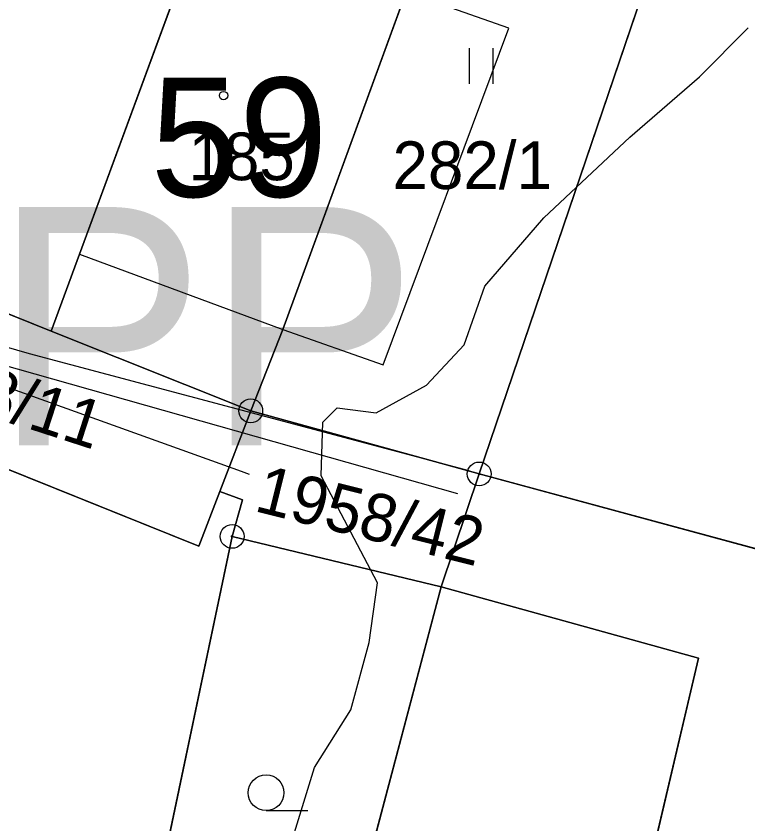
# Model space of a CAD drawing. Extents: x -706130 to -698555, y -971544 to -967260.
# Drawn here: x -704307.34 to -704276.64, y -970193.24 to -970159.33 of the extents above; entities that cross this region are included whole.
import ezdxf

# ---------------------------------------------------------------- set-up
doc = ezdxf.new("R2010")
doc.units = 0
for name, color, linetype in [('_Doplněk budov pro zastavěnost', 7, 'Continuous'), ('BPEJ I-II trida ochrany S', 7, 'Continuous'), ('Docházková izochrona - BUS S', 7, 'Continuous'), ('Docházková izochrona - VLAK N', 7, 'Continuous'), ('Kanalizace_stoka bez rozlišení N', 7, 'Continuous'), ('KN_Budovy', 7, 'Continuous'), ('KN_Budovy_cisla_domovni', 7, 'Continuous'), ('KN_Hranice_parcel', 7, 'Continuous'), ('KN_Hranice_parcel_vnitrni_kresba', 7, 'Continuous'), ('KN_Parcelni cisla', 7, 'Continuous'), ('KN_Polygon parcely', 7, 'Continuous'), ('KN_POZEMKY_13_ZASTAVENA PLOCHA', 7, 'Continuous'), ('KN_POZEMKY_14_OSTATNI PLOCHA', 7, 'Continuous'), ('KN_POZEMKY_5_ZAHRADA', 7, 'Continuous'), ('KN_POZEMKY_7_TTP', 7, 'Continuous'), ('KN_VYUZITI_17_ostatni plocha_ostatni komunikace', 7, 'Continuous'), ('KN_Značky bodu BP', 7, 'Continuous'), ('KN_Značky budov', 7, 'Continuous'), ('KN_Značky kultur', 7, 'Continuous'), ('Plochy smíšené obytné venkovské S', 7, 'Continuous'), ('Plochy verejnych prostranstvi - komunikace ostatni S', 7, 'Continuous'), ('Plynovody STL S', 7, 'Continuous'), ('Regulační bloky zastavěné S', 7, 'Continuous'), ('Regulační kódy zastavěné S', 7, 'Continuous'), ('Vodovodní řady - rozváděcí S', 7, 'Continuous'), ('Záplavové území stanovene S', 7, 'Continuous')]:
    doc.layers.add(name, color=color, linetype=linetype)

msp = doc.modelspace()

# ---------------------------------------------------------------- linework, layer by layer
at = {"layer": '_Doplněk budov pro zastavěnost'}
msp.add_line((-704290.97, -970158.31), (-704296.15, -970172.48), dxfattribs=at)
msp.add_lwpolyline([(-704296.15, -970172.48), (-704291.936, -970173.974), (-704286.668, -970159.832), (-704290.97, -970158.31)], dxfattribs=at)
at = {"layer": 'BPEJ I-II trida ochrany S'}
for p, q in [((-704304.68, -970169.32), (-704299.48, -970155.18)), ((-704290.97, -970158.31), (-704296.15, -970172.48)), ((-704313.84, -970169.35), (-704305.87, -970172.55)), ((-704305.87, -970172.55), (-704304.68, -970169.32)), ((-704296.15, -970172.48), (-704297.5, -970175.9)), ((-704297.5, -970175.9), (-704287.91, -970178.55)), ((-704287.91, -970178.55), (-704274.42, -970182.2)), ((-704298.28, -970181.17), (-704303.37, -970205.4)), ((-704289.51, -970183.29), (-704298.28, -970181.17)), ((-704278.71, -970186.28), (-704289.51, -970183.29)), ((-704281.59, -970198.52), (-704278.71, -970186.28))]:
    msp.add_line(p, q, dxfattribs=at)
at = {"layer": 'Docházková izochrona - BUS S'}
msp.add_arc((-704361.829, -969946.93), 400, 155.51821, 17.33949, dxfattribs=at)
at = {"layer": 'Docházková izochrona - VLAK N'}
msp.add_circle((-704165.451, -969778.767), 800, dxfattribs=at)
at = {"layer": 'Kanalizace_stoka bez rozlišení N'}
msp.add_lwpolyline([(-704326.245, -970169.76), (-704311.212, -970173.028), (-704288.826, -970179.373)], dxfattribs=at)
at = {"layer": 'KN_Budovy'}
msp.add_lwpolyline([(-704299.48, -970155.18), (-704304.68, -970169.32), (-704296.15, -970172.48), (-704290.97, -970158.31)], close=True, dxfattribs=at)
at = {"layer": 'KN_Hranice_parcel'}
for p, q in [((-704287.91, -970178.55), (-704277.5, -970147.92)), ((-704313.84, -970169.35), (-704305.87, -970172.55)), ((-704305.87, -970172.55), (-704297.5, -970175.9)), ((-704298.79, -970179.28), (-704297.5, -970175.9)), ((-704297.5, -970175.9), (-704287.91, -970178.55)), ((-704287.91, -970178.55), (-704289.51, -970183.29)), ((-704303.37, -970205.4), (-704298.28, -970181.17)), ((-704289.51, -970183.29), (-704298.28, -970181.17)), ((-704289.51, -970183.29), (-704295.97, -970207.7))]:
    msp.add_line(p, q, dxfattribs=at)
for points in [[(-704290.97, -970158.31), (-704299.48, -970155.18), (-704304.68, -970169.32), (-704305.87, -970172.55)], [(-704297.5, -970175.9), (-704296.15, -970172.48), (-704290.97, -970158.31)], [(-704229.48, -970192.46), (-704233.16, -970192.68), (-704246.9, -970190.81), (-704243.81, -970184.46), (-704246.58, -970183.12), (-704250.99, -970180.98), (-704248.44, -970175.82), (-704254.77, -970172.57), (-704251.76, -970166.35), (-704257.7, -970163.48), (-704260.71, -970169.69), (-704266.92, -970166.69), (-704270.32, -970173.72), (-704274.42, -970182.2), (-704287.91, -970178.55)], [(-704298.79, -970179.28), (-704299.67, -970181.58), (-704316.23, -970174.92), (-704322.1, -970177.43), (-704324.27, -970184.8)], [(-704298.28, -970181.17), (-704297.85, -970179.64), (-704298.79, -970179.28)], [(-704289.51, -970183.29), (-704278.71, -970186.28), (-704281.59, -970198.52), (-704273.81, -970199.62), (-704275.41, -970210.91)]]:
    msp.add_lwpolyline(points, dxfattribs=at)
at = {"layer": 'KN_Hranice_parcel_vnitrni_kresba'}
msp.add_line((-704304.68, -970169.32), (-704296.15, -970172.48), dxfattribs=at)
at = {"layer": 'KN_Polygon parcely'}
for points in [[(-704305.87, -970172.55), (-704304.68, -970169.32), (-704299.48, -970155.18), (-704290.97, -970158.31), (-704288.36, -970145.25), (-704300.38, -970142.47), (-704313.84, -970169.35)], [(-704287.91, -970178.55), (-704277.5, -970147.92), (-704288.36, -970145.25), (-704290.97, -970158.31), (-704296.15, -970172.48), (-704297.5, -970175.9)], [(-704229.48, -970192.46), (-704222.31, -970155.39), (-704260.52, -970150.22), (-704277.5, -970147.92), (-704287.91, -970178.55), (-704274.42, -970182.2), (-704270.32, -970173.72), (-704266.92, -970166.69), (-704260.71, -970169.69), (-704257.7, -970163.48), (-704251.76, -970166.35), (-704254.77, -970172.57), (-704248.44, -970175.82), (-704250.99, -970180.98), (-704246.58, -970183.12), (-704243.81, -970184.46), (-704246.9, -970190.81), (-704233.16, -970192.68)], [(-704290.97, -970158.31), (-704299.48, -970155.18), (-704304.68, -970169.32), (-704305.87, -970172.55), (-704297.5, -970175.9), (-704296.15, -970172.48)], [(-704297.5, -970175.9), (-704305.87, -970172.55), (-704313.84, -970169.35), (-704322.68, -970165.89), (-704322.52, -970176.47), (-704324.27, -970184.8), (-704322.1, -970177.43), (-704316.23, -970174.92), (-704299.67, -970181.58), (-704298.79, -970179.28)], [(-704316.23, -970174.92), (-704322.1, -970177.43), (-704324.27, -970184.8), (-704325.58, -970189.23), (-704327.21, -970194.48), (-704328.2, -970197.68), (-704303.37, -970205.4), (-704298.28, -970181.17), (-704297.85, -970179.64), (-704298.79, -970179.28), (-704299.67, -970181.58)], [(-704298.79, -970179.28), (-704297.85, -970179.64), (-704298.28, -970181.17), (-704289.51, -970183.29), (-704287.91, -970178.55), (-704297.5, -970175.9)], [(-704303.37, -970205.4), (-704295.97, -970207.7), (-704289.51, -970183.29), (-704298.28, -970181.17)], [(-704289.51, -970183.29), (-704295.97, -970207.7), (-704281.8, -970209.65), (-704275.41, -970210.91), (-704273.81, -970199.62), (-704281.59, -970198.52), (-704278.71, -970186.28)]]:
    msp.add_lwpolyline(points, close=True, dxfattribs=at)
msp.add_lwpolyline([(-704230.21, -970196.19), (-704229.48, -970192.46), (-704233.16, -970192.68), (-704246.9, -970190.81), (-704243.81, -970184.46), (-704246.58, -970183.12), (-704250.99, -970180.98), (-704248.44, -970175.82), (-704254.77, -970172.57), (-704251.76, -970166.35), (-704257.7, -970163.48), (-704260.71, -970169.69), (-704266.92, -970166.69), (-704270.32, -970173.72), (-704274.42, -970182.2), (-704287.91, -970178.55), (-704289.51, -970183.29), (-704278.71, -970186.28), (-704281.59, -970198.52)], dxfattribs=at)
at = {"layer": 'KN_POZEMKY_13_ZASTAVENA PLOCHA'}
for p, q in [((-704304.68, -970169.32), (-704299.48, -970155.18)), ((-704290.97, -970158.31), (-704296.15, -970172.48)), ((-704305.87, -970172.55), (-704304.68, -970169.32)), ((-704296.15, -970172.48), (-704297.5, -970175.9)), ((-704297.5, -970175.9), (-704305.87, -970172.55)), ((-704316.23, -970174.92), (-704299.67, -970181.58)), ((-704289.51, -970183.29), (-704287.91, -970178.55)), ((-704287.91, -970178.55), (-704274.42, -970182.2)), ((-704299.67, -970181.58), (-704298.79, -970179.28)), ((-704298.79, -970179.28), (-704297.85, -970179.64)), ((-704297.85, -970179.64), (-704298.28, -970181.17)), ((-704298.28, -970181.17), (-704303.37, -970205.4)), ((-704278.71, -970186.28), (-704289.51, -970183.29)), ((-704281.59, -970198.52), (-704278.71, -970186.28))]:
    msp.add_line(p, q, dxfattribs=at)
at = {"layer": 'KN_POZEMKY_14_OSTATNI PLOCHA'}
for p, q in [((-704313.84, -970169.35), (-704305.87, -970172.55)), ((-704305.87, -970172.55), (-704297.5, -970175.9)), ((-704299.67, -970181.58), (-704316.23, -970174.92)), ((-704297.5, -970175.9), (-704298.79, -970179.28)), ((-704298.79, -970179.28), (-704297.5, -970175.9)), ((-704297.5, -970175.9), (-704287.91, -970178.55)), ((-704287.91, -970178.55), (-704289.51, -970183.29)), ((-704298.79, -970179.28), (-704299.67, -970181.58)), ((-704297.85, -970179.64), (-704298.79, -970179.28)), ((-704298.28, -970181.17), (-704297.85, -970179.64)), ((-704289.51, -970183.29), (-704298.28, -970181.17))]:
    msp.add_line(p, q, dxfattribs=at)
at = {"layer": 'KN_POZEMKY_5_ZAHRADA'}
for p, q in [((-704299.48, -970155.18), (-704304.68, -970169.32)), ((-704305.87, -970172.55), (-704313.84, -970169.35)), ((-704304.68, -970169.32), (-704305.87, -970172.55)), ((-704303.37, -970205.4), (-704298.28, -970181.17)), ((-704298.28, -970181.17), (-704289.51, -970183.29)), ((-704295.97, -970207.7), (-704289.51, -970183.29)), ((-704289.51, -970183.29), (-704295.97, -970207.7)), ((-704289.51, -970183.29), (-704278.71, -970186.28)), ((-704278.71, -970186.28), (-704281.59, -970198.52))]:
    msp.add_line(p, q, dxfattribs=at)
at = {"layer": 'KN_POZEMKY_7_TTP'}
for p, q in [((-704287.91, -970178.55), (-704277.5, -970147.92)), ((-704277.5, -970147.92), (-704287.91, -970178.55)), ((-704296.15, -970172.48), (-704290.97, -970158.31)), ((-704297.5, -970175.9), (-704296.15, -970172.48)), ((-704287.91, -970178.55), (-704297.5, -970175.9)), ((-704274.42, -970182.2), (-704287.91, -970178.55))]:
    msp.add_line(p, q, dxfattribs=at)
at = {"layer": 'KN_VYUZITI_17_ostatni plocha_ostatni komunikace'}
for p, q in [((-704313.84, -970169.35), (-704305.87, -970172.55)), ((-704305.87, -970172.55), (-704297.5, -970175.9)), ((-704299.67, -970181.58), (-704316.23, -970174.92)), ((-704297.5, -970175.9), (-704298.79, -970179.28)), ((-704298.79, -970179.28), (-704297.5, -970175.9)), ((-704297.5, -970175.9), (-704287.91, -970178.55)), ((-704287.91, -970178.55), (-704289.51, -970183.29)), ((-704298.79, -970179.28), (-704299.67, -970181.58)), ((-704297.85, -970179.64), (-704298.79, -970179.28)), ((-704298.28, -970181.17), (-704297.85, -970179.64)), ((-704289.51, -970183.29), (-704298.28, -970181.17))]:
    msp.add_line(p, q, dxfattribs=at)
at = {"layer": 'KN_Značky bodu BP'}
for centre, radius in [((-704297.5, -970175.9), 0.5), ((-704297.5, -970175.9), 0.0303), ((-704287.91, -970178.55), 0.5), ((-704287.91, -970178.55), 0.0303), ((-704298.28, -970181.17), 0.5), ((-704298.28, -970181.17), 0.0303)]:
    msp.add_circle(centre, radius, dxfattribs=at)
at = {"layer": 'KN_Značky budov'}
msp.add_circle((-704298.637, -970162.669), 0.175, dxfattribs=at)
at = {"layer": 'KN_Značky kultur'}
for p, q in [((-704288.321, -970162.18), (-704288.321, -970160.68)), ((-704287.32, -970162.18), (-704287.32, -970160.68)), ((-704296.853, -970192.68), (-704295.103, -970192.68))]:
    msp.add_line(p, q, dxfattribs=at)
msp.add_circle((-704296.853, -970191.93), 0.75, dxfattribs=at)
at = {"layer": 'Plochy smíšené obytné venkovské S'}
for p, q in [((-704313.84, -970169.35), (-704305.87, -970172.55)), ((-704305.87, -970172.55), (-704297.5, -970175.9)), ((-704297.5, -970175.9), (-704287.91, -970178.55)), ((-704287.91, -970178.55), (-704289.51, -970183.29)), ((-704298.79, -970179.28), (-704299.67, -970181.58)), ((-704289.51, -970183.29), (-704298.28, -970181.17))]:
    msp.add_line(p, q, dxfattribs=at)
for points in [[(-704299.67, -970181.58), (-704316.23, -970174.92), (-704322.1, -970177.43)], [(-704298.28, -970181.17), (-704297.85, -970179.64), (-704298.79, -970179.28)]]:
    msp.add_lwpolyline(points, dxfattribs=at)
at = {"layer": 'Plochy verejnych prostranstvi - komunikace ostatni S'}
for p, q in [((-704305.87, -970172.55), (-704313.84, -970169.35)), ((-704297.5, -970175.9), (-704305.87, -970172.55)), ((-704287.91, -970178.55), (-704297.5, -970175.9)), ((-704289.51, -970183.29), (-704287.91, -970178.55)), ((-704298.28, -970181.17), (-704289.51, -970183.29))]:
    msp.add_line(p, q, dxfattribs=at)
for points in [[(-704322.1, -970177.43), (-704316.23, -970174.92), (-704299.67, -970181.58), (-704298.79, -970179.28)], [(-704298.79, -970179.28), (-704297.85, -970179.64), (-704298.28, -970181.17)]]:
    msp.add_lwpolyline(points, dxfattribs=at)
at = {"layer": 'Plynovody STL S'}
msp.add_lwpolyline([(-704323.56, -970172.21), (-704321.3, -970172.54), (-704311.5, -970173.55), (-704297.9, -970178.44), (-704297.571, -970178.559)], dxfattribs=at)
at = {"layer": 'Regulační bloky zastavěné S'}
for p, q in [((-704305.87, -970172.55), (-704313.84, -970169.35)), ((-704313.84, -970169.35), (-704305.87, -970172.55)), ((-704297.5, -970175.9), (-704305.87, -970172.55)), ((-704305.87, -970172.55), (-704297.5, -970175.9)), ((-704287.91, -970178.55), (-704297.5, -970175.9)), ((-704297.5, -970175.9), (-704287.91, -970178.55)), ((-704289.51, -970183.29), (-704287.91, -970178.55)), ((-704287.91, -970178.55), (-704289.51, -970183.29)), ((-704298.79, -970179.28), (-704299.67, -970181.58)), ((-704298.28, -970181.17), (-704289.51, -970183.29)), ((-704289.51, -970183.29), (-704298.28, -970181.17))]:
    msp.add_line(p, q, dxfattribs=at)
for points in [[(-704322.1, -970177.43), (-704316.23, -970174.92), (-704299.67, -970181.58), (-704298.79, -970179.28)], [(-704299.67, -970181.58), (-704316.23, -970174.92), (-704322.1, -970177.43)], [(-704298.79, -970179.28), (-704297.85, -970179.64), (-704298.28, -970181.17)], [(-704298.28, -970181.17), (-704297.85, -970179.64), (-704298.79, -970179.28)]]:
    msp.add_lwpolyline(points, dxfattribs=at)
at = {"layer": 'Vodovodní řady - rozváděcí S'}
msp.add_lwpolyline([(-704322.37, -970168.99), (-704306.79, -970173.5), (-704288.34, -970178.4)], dxfattribs=at)
at = {"layer": 'Záplavové území stanovene S'}
msp.add_lwpolyline([(-704296.823, -970197.375), (-704294.823, -970190.875), (-704293.293, -970188.457), (-704292.527, -970185.626), (-704292.172, -970183.125), (-704294.547, -970178.625), (-704294.469, -970176.375), (-704293.875, -970175.781), (-704292.229, -970175.979), (-704290.125, -970174.828), (-704288.547, -970173.125), (-704287.672, -970170.672), (-704285.194, -970167.806), (-704281.586, -970164.414), (-704278.672, -970161.875), (-704276.625, -970159.828)], dxfattribs=at)

# ---------------------------------------------------------------- texts
at = {"layer": 'KN_Budovy_cisla_domovni'}
msp.add_text('59', height=5, dxfattribs=at).set_placement((-704301.708, -970166.919))
at = {"layer": 'KN_Parcelni cisla'}
for s, p in [('185', (-704300.11, -970166.22)), ('282/1', (-704291.55, -970166.59))]:
    msp.add_text(s, height=2, dxfattribs=at).set_placement(p)
for s, rotation, p in [('1958/11', 342, (-704313.292, -970174.548)), ('1958/42', 346, (-704297.405, -970180.094))]:
    msp.add_text(s, height=2, rotation=rotation, dxfattribs=at).set_placement(p)
at = {"layer": 'Regulační kódy zastavěné S'}
msp.add_text('PP', height=10, dxfattribs=at).set_placement((-704308.32, -970177.347))

doc.saveas('drawing.dxf')
